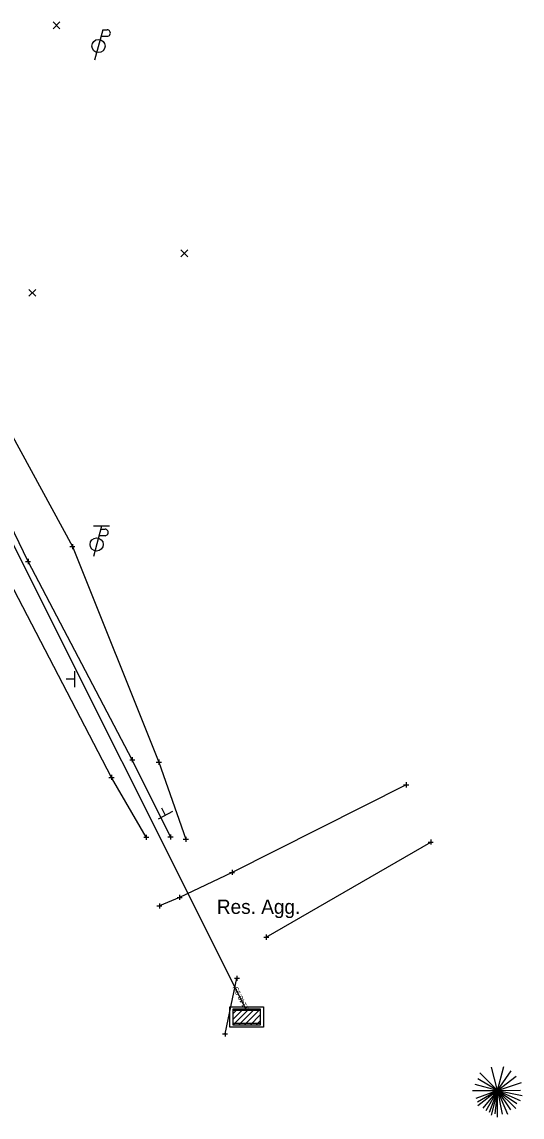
# Model space of a CAD drawing. Extents: x 2298098 to 2302860, y 557788 to 564251.
# Drawn here: x 2299057.3 to 2299155.9, y 562466.8 to 562682.6 of the extents above; entities that cross this region are included whole.
import ezdxf

# ---------------------------------------------------------------- set-up
doc = ezdxf.new("R2010")
doc.units = 0
for name, color, linetype in [('DR_X_Cells', 7, 'Continuous'), ('DR_X_Ditch', 7, 'Continuous'), ('DR_X_Storm_Sewer', 7, 'Continuous'), ('GK_Drainage_Nodes', 7, 'Continuous'), ('PV_X_Driveway', 7, 'Continuous'), ('PV_X_Text', 7, 'Continuous'), ('SC_Scratch1', 7, 'Continuous'), ('SN_X_Public', 7, 'Continuous'), ('SV_X_Break_Lines', 7, 'Continuous'), ('SV_X_Random_Point', 7, 'Continuous'), ('SV_X_Shot_Marker', 7, 'Continuous'), ('UT_X_Electric_Cells', 7, 'Continuous'), ('UT_X_Misc_Cells', 7, 'Continuous'), ('VG_X_Cells', 7, 'Continuous')]:
    doc.layers.add(name, color=color, linetype=linetype)

msp = doc.modelspace()

# ---------------------------------------------------------------- linework, layer by layer
at = {"layer": 'DR_X_Cells'}
for p, q in [((2299098.96, 562485), (2299102.14, 562488.18)), ((2299098.96, 562486.13), (2299101.01, 562488.18)), ((2299098.96, 562487.26), (2299099.88, 562488.18)), ((2299100.04, 562484.96), (2299103.27, 562488.18)), ((2299101.17, 562484.96), (2299104.29, 562488.07)), ((2299102.3, 562484.96), (2299104.29, 562486.94)), ((2299103.43, 562484.96), (2299104.29, 562485.81))]:
    msp.add_line(p, q, dxfattribs=at)
for points in [[(2299098.29, 562488.57), (2299104.96, 562488.57), (2299104.96, 562484.57), (2299098.29, 562484.57)], [(2299098.96, 562488.18), (2299104.29, 562488.18), (2299104.29, 562484.96), (2299098.96, 562484.96)], [(2299098.96, 562487.9), (2299104.29, 562487.9), (2299104.29, 562485.24), (2299098.96, 562485.24)]]:
    msp.add_lwpolyline(points, close=True, dxfattribs=at)
at = {"layer": 'DR_X_Ditch'}
msp.add_lwpolyline([(2299086.62, 562522.02), (2299079.1, 562537.23), (2299058.55, 562576.3), (2299036.88, 562621.13)], dxfattribs=at)
at = {"layer": 'DR_X_Storm_Sewer'}
msp.add_line((2299101.62, 562487.9), (2299032.08, 562626.58), dxfattribs=at)
at = {"layer": 'GK_Drainage_Nodes'}
for p, q in [((2299101.62, 562488.57), (2299101.62, 562488.57)), ((2299098.96, 562486.57), (2299098.96, 562486.57)), ((2299101.62, 562487.9), (2299101.62, 562487.9)), ((2299101.62, 562486.57), (2299101.62, 562486.57)), ((2299101.62, 562486.57), (2299101.62, 562486.57)), ((2299104.29, 562486.57), (2299104.29, 562486.57)), ((2299101.62, 562485.24), (2299101.62, 562485.24)), ((2299101.62, 562484.96), (2299101.62, 562484.96)), ((2299101.62, 562484.57), (2299101.62, 562484.57))]:
    msp.add_line(p, q, dxfattribs=at)
at = {"layer": 'PV_X_Driveway'}
for p, q in [((2299105.51, 562502.27), (2299137.91, 562521.02)), ((2299097.39, 562483.21), (2299099.72, 562494.17))]:
    msp.add_line(p, q, dxfattribs=at)
msp.add_lwpolyline([(2299133.08, 562532.3), (2299098.75, 562515.04), (2299088.41, 562510.11), (2299084.43, 562508.42)], dxfattribs=at)
at = {"layer": 'SN_X_Public'}
for p, q in [((2299067.68, 562553.12), (2299066.08, 562553.12)), ((2299067.68, 562554.72), (2299067.68, 562551.52)), ((2299087.05, 562527.02), (2299084.22, 562525.52)), ((2299085.64, 562526.27), (2299084.89, 562527.68))]:
    msp.add_line(p, q, dxfattribs=at)
at = {"layer": 'SV_X_Break_Lines'}
for points in [[(2299043.17, 562623.49), (2299067.28, 562579.23), (2299084.33, 562536.76), (2299089.65, 562521.58)], [(2299081.84, 562521.95), (2299074.99, 562533.75), (2299053.19, 562575.69), (2299034.27, 562619.34)]]:
    msp.add_lwpolyline(points, dxfattribs=at)
at = {"layer": 'SV_X_Random_Point'}
for p, q in [((2299063.47, 562681.3), (2299064.8, 562682.63)), ((2299063.47, 562682.63), (2299064.8, 562681.3)), ((2299088.69, 562636.37), (2299090.02, 562637.71)), ((2299088.69, 562637.71), (2299090.02, 562636.37)), ((2299058.72, 562628.59), (2299060.05, 562629.93)), ((2299058.72, 562629.93), (2299060.05, 562628.59))]:
    msp.add_line(p, q, dxfattribs=at)
at = {"layer": 'SV_X_Shot_Marker'}
for p, q in [((2299066.78, 562579.23), (2299067.78, 562579.23)), ((2299067.28, 562579.73), (2299067.28, 562578.73)), ((2299067.28, 562579.23), (2299067.28, 562579.23)), ((2299058.55, 562576.8), (2299058.55, 562575.8)), ((2299058.05, 562576.3), (2299059.05, 562576.3)), ((2299058.55, 562576.3), (2299058.55, 562576.3)), ((2299078.6, 562537.23), (2299079.6, 562537.23)), ((2299079.1, 562537.73), (2299079.1, 562536.73)), ((2299079.1, 562537.23), (2299079.1, 562537.23)), ((2299083.83, 562536.76), (2299084.83, 562536.76)), ((2299084.33, 562537.26), (2299084.33, 562536.26)), ((2299084.33, 562536.76), (2299084.33, 562536.76)), ((2299074.49, 562533.75), (2299075.49, 562533.75)), ((2299074.99, 562534.25), (2299074.99, 562533.25)), ((2299074.99, 562533.75), (2299074.99, 562533.75)), ((2299132.58, 562532.3), (2299133.58, 562532.3)), ((2299133.08, 562532.8), (2299133.08, 562531.8)), ((2299133.08, 562532.3), (2299133.08, 562532.3)), ((2299081.34, 562521.95), (2299082.34, 562521.95)), ((2299081.84, 562522.45), (2299081.84, 562521.45)), ((2299081.84, 562521.95), (2299081.84, 562521.95)), ((2299086.12, 562522.02), (2299087.12, 562522.02)), ((2299086.62, 562522.52), (2299086.62, 562521.52)), ((2299086.62, 562522.02), (2299086.62, 562522.02)), ((2299089.15, 562521.58), (2299090.15, 562521.58)), ((2299089.65, 562522.08), (2299089.65, 562521.08)), ((2299089.65, 562521.58), (2299089.65, 562521.58)), ((2299137.41, 562521.02), (2299138.41, 562521.02)), ((2299137.91, 562521.52), (2299137.91, 562520.52)), ((2299137.91, 562521.02), (2299137.91, 562521.02)), ((2299098.25, 562515.04), (2299099.25, 562515.04)), ((2299098.75, 562515.54), (2299098.75, 562514.54)), ((2299098.75, 562515.04), (2299098.75, 562515.04)), ((2299087.91, 562510.11), (2299088.91, 562510.11)), ((2299088.41, 562510.61), (2299088.41, 562509.61)), ((2299088.41, 562510.11), (2299088.41, 562510.11)), ((2299083.93, 562508.42), (2299084.93, 562508.42)), ((2299084.43, 562508.92), (2299084.43, 562507.92)), ((2299084.43, 562508.42), (2299084.43, 562508.42)), ((2299105.01, 562502.27), (2299106.01, 562502.27)), ((2299105.51, 562502.77), (2299105.51, 562501.77)), ((2299105.51, 562502.27), (2299105.51, 562502.27)), ((2299099.72, 562494.67), (2299099.72, 562493.67)), ((2299099.22, 562494.17), (2299100.22, 562494.17)), ((2299099.72, 562494.17), (2299099.72, 562494.17)), ((2299096.89, 562483.21), (2299097.89, 562483.21)), ((2299097.39, 562483.71), (2299097.39, 562482.71)), ((2299097.39, 562483.21), (2299097.39, 562483.21))]:
    msp.add_line(p, q, dxfattribs=at)
at = {"layer": 'UT_X_Electric_Cells'}
for p, q in [((2299073.27, 562681.08), (2299071.67, 562675.08)), ((2299073.27, 562681.08), (2299074.12, 562681.08)), ((2299072.93, 562679.8), (2299074.12, 562679.8))]:
    msp.add_line(p, q, dxfattribs=at)
msp.add_circle((2299072.42, 562677.88), 1.3, dxfattribs=at)
msp.add_arc((2299074.14, 562680.44), 0.638, 268.8767, 91.1233, dxfattribs=at)
at = {"layer": 'UT_X_Misc_Cells'}
for p, q in [((2299073.03, 562583.27), (2299071.42, 562577.27)), ((2299074.63, 562583.27), (2299071.43, 562583.27)), ((2299072.52, 562581.4), (2299073.72, 562581.4)), ((2299072.87, 562582.67), (2299073.72, 562582.67))]:
    msp.add_line(p, q, dxfattribs=at)
msp.add_circle((2299072.06, 562579.67), 1.3, dxfattribs=at)
msp.add_arc((2299073.73, 562582.03), 0.638, 268.8767, 91.1233, dxfattribs=at)
at = {"layer": 'VG_X_Cells'}
for p, q in [((2299151.1, 562472.06), (2299147.61, 562475.55)), ((2299151.1, 562472.06), (2299149.87, 562476.67)), ((2299151.1, 562472.06), (2299152.36, 562476.76)), ((2299151.1, 562472.06), (2299153.76, 562475.94)), ((2299151.1, 562472.06), (2299146.69, 562473.24)), ((2299151.1, 562472.06), (2299147.19, 562474.36)), ((2299151.1, 562472.06), (2299154.76, 562474.86)), ((2299151.1, 562472.06), (2299155.84, 562473.67)), ((2299146.17, 562472.06), (2299151.1, 562472.06)), ((2299151.1, 562472.06), (2299146.81, 562470.5)), ((2299151.1, 562472.06), (2299147.12, 562469.78)), ((2299151.1, 562472.06), (2299147.19, 562469.06)), ((2299151.1, 562472.06), (2299148.16, 562468.59)), ((2299151.1, 562472.06), (2299148.78, 562468.04)), ((2299151.1, 562472.06), (2299149.44, 562467.72)), ((2299151.1, 562472.06), (2299149.84, 562467.2)), ((2299151.1, 562472.06), (2299150.56, 562467.47)), ((2299151.1, 562472.06), (2299155.61, 562472.15)), ((2299151.1, 562466.82), (2299151.1, 562472.06)), ((2299151.1, 562472.06), (2299152.02, 562467.42)), ((2299151.1, 562472.06), (2299153.03, 562467.39)), ((2299151.1, 562472.06), (2299153.64, 562468.27)), ((2299151.1, 562472.06), (2299154.69, 562468.54)), ((2299151.1, 562472.06), (2299154.92, 562469.51)), ((2299151.1, 562472.06), (2299155.57, 562470.12)), ((2299151.1, 562472.06), (2299155.93, 562471.1))]:
    msp.add_line(p, q, dxfattribs=at)

# ---------------------------------------------------------------- texts
at = {"layer": 'PV_X_Text'}
msp.add_text('Res. Agg.', height=2.8, dxfattribs=at).set_placement((2299095.77, 562506.87))
at = {"layer": 'SC_Scratch1'}
msp.add_text("1148.99'", height=1, rotation=116.6334, dxfattribs=at).set_placement((2299102.07, 562488.13))

doc.saveas('drawing.dxf')
